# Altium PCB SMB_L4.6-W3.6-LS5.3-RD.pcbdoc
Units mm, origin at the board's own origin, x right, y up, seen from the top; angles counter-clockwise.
Board outline 19.47 x 16.62 mm, 2 copper layers (Top Layer, Bottom Layer), stack 0 mm thick; 1 components, 0 nets, 2 pads, 0 vias.
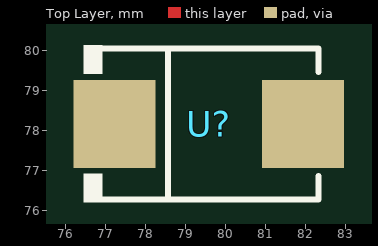
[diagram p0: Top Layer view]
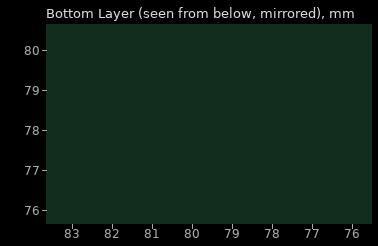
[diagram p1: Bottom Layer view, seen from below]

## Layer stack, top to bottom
Top Layer: signal copper (thickness not stored)
Bottom Layer: signal copper (thickness not stored)

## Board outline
89.319,69.85 69.85,69.85 69.85,86.475 89.319,86.475

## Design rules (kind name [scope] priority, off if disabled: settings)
PasteMaskExpansion "Paste Mask Expansion" [All] p1: expansion=0
SolderMaskExpansion "Solder Mask Expansion" [IsVia] p1: expansion=-25.4 istentingtop=TRUE
SolderMaskExpansion "Solder Mask Expansion" [All] p2: expansion=0.051 istentingtop=FALSE

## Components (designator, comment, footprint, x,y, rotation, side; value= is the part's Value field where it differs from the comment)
U? "" SMB_L4.6-W3.6-LS5.3-RD 79.584,78.162 r0 top

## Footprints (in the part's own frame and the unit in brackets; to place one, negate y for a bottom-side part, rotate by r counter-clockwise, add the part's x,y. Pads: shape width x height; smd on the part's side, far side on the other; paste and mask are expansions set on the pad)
SMB_L4.6-W3.6-LS5.3-RD [mm]
  rect 2.047x2.192 smd: 1(-2.361,0) 2(2.361,0)
  silkscreen extent -3.12,-1.96 2.74,1.96

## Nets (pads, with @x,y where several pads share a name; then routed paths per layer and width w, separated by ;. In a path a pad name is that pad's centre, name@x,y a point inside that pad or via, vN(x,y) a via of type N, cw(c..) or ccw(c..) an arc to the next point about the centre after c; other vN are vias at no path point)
pads on no net: U?.1 U?.2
